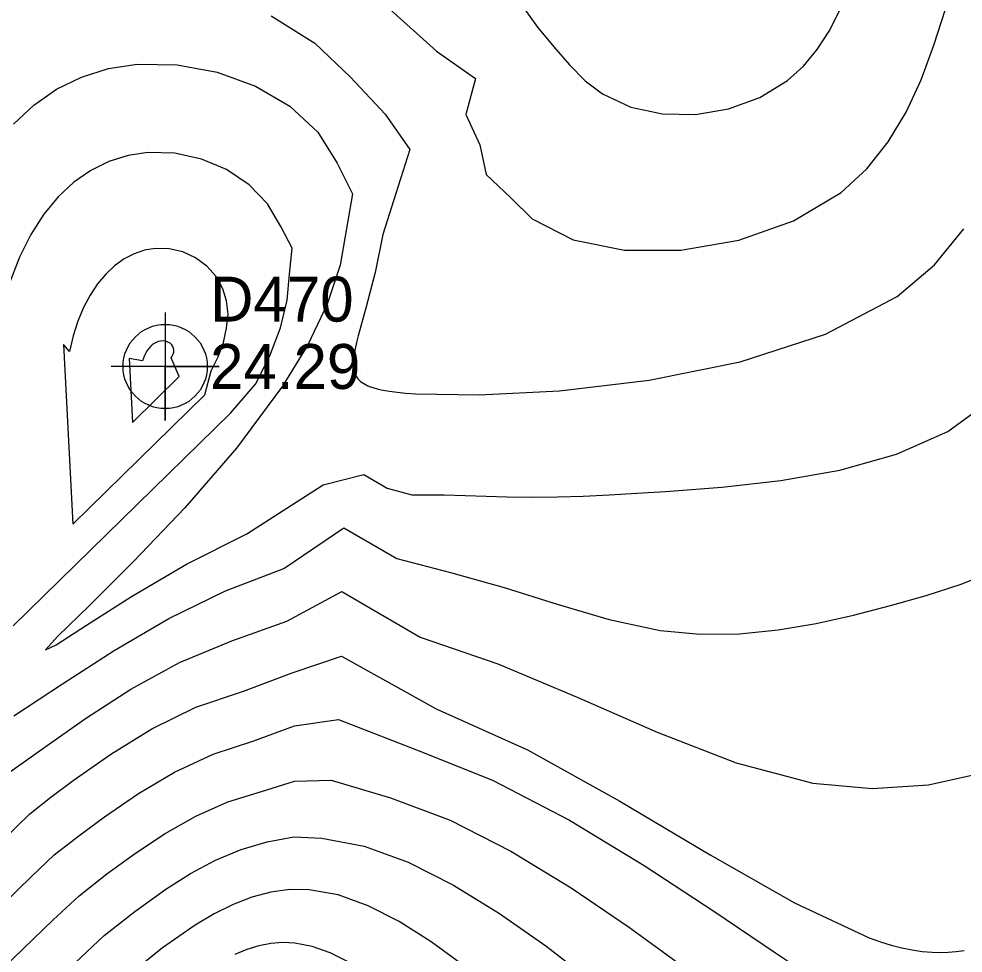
# Model space of a CAD drawing. Extents: x 2356077 to 2359823, y 225951 to 227822.
# Drawn here: x 2356716.3 to 2356768.9, y 226939 to 226991.1 of the extents above; entities that cross this region are included whole.
import ezdxf

# ---------------------------------------------------------------- set-up
doc = ezdxf.new("R2010")
doc.units = 0
for name, color, linetype in [('DTM Contours Major', 7, 'Continuous'), ('DTM Contours Minor', 7, 'Continuous'), ('Exist DTM Regular Point CELL', 7, 'Continuous'), ('Exist DTM Regular Point Cogo Elevation', 7, 'Continuous'), ('Exist DTM Regular Point Cogo Number', 7, 'Continuous'), ('PH Exist DTM Point', 7, 'Continuous')]:
    doc.layers.add(name, color=color, linetype=linetype)

msp = doc.modelspace()

# ---------------------------------------------------------------- linework, layer by layer
at = {"layer": 'DTM Contours Major'}
for points in [[(2356716.024, 226985.191), (2356717.155, 226986.252), (2356718.423, 226987.128), (2356719.815, 226987.808), (2356721.316, 226988.279), (2356722.912, 226988.527), (2356725.134, 226988.5), (2356727.373, 226988.084), (2356729.508, 226987.303), (2356731.415, 226986.182), (2356732.97, 226984.744), (2356734.05, 226983.015), (2356734.908, 226981.299), (2356734.219, 226977.331), (2356733.487, 226975.163), (2356732.407, 226972.908), (2356731.006, 226970.595), (2356728.435, 226967.137), (2356725.559, 226963.817), (2356722.717, 226960.834), (2356720.252, 226958.389), (2356718.504, 226956.685), (2356717.816, 226955.921), (2356718.408, 226956.202), (2356720.092, 226957.29), (2356722.601, 226958.884), (2356725.666, 226960.681), (2356729.019, 226962.379), (2356733.274, 226965.1), (2356735.538, 226965.678), (2356736.833, 226964.921), (2356738.198, 226964.553), (2356740.006, 226964.551), (2356743.514, 226964.435), (2356744.911, 226964.419), (2356746.317, 226964.435), (2356747.746, 226964.478), (2356749.215, 226964.546), (2356750.739, 226964.633), (2356752.333, 226964.737), (2356755.469, 226964.976), (2356758.754, 226965.343), (2356762.042, 226965.926), (2356765.188, 226966.811), (2356768.047, 226968.083), (2356770.473, 226969.83)], [(2356715.459, 226938.194), (2356718.23, 226940.885), (2356719.678, 226942.225), (2356721.223, 226943.438), (2356722.82, 226944.602), (2356724.468, 226945.689), (2356726.178, 226946.656), (2356727.962, 226947.453), (2356729.828, 226948.028), (2356731.677, 226948.606), (2356733.716, 226948.667), (2356737.016, 226947.683), (2356740.333, 226946.426), (2356743.716, 226944.701), (2356747.078, 226942.658), (2356750.334, 226940.449), (2356753.397, 226938.225)]]:
    msp.add_lwpolyline(points, dxfattribs=at)
at = {"layer": 'DTM Contours Minor'}
for points in [[(2356737, 226991.578), (2356739.576, 226989.257), (2356741.758, 226987.723), (2356741.21, 226985.73), (2356741.994, 226984.046), (2356742.353, 226982.378), (2356743.717, 226981.081), (2356744.899, 226979.922), (2356747.199, 226978.753), (2356750.043, 226978.18), (2356753.194, 226978.179), (2356756.414, 226978.729), (2356759.466, 226979.806), (2356762.114, 226981.388), (2356763.545, 226982.698), (2356764.735, 226984.196), (2356765.727, 226985.858), (2356766.561, 226987.661), (2356767.278, 226989.582), (2356767.919, 226991.597)], [(2356744.351, 226991.776), (2356745.197, 226990.593), (2356746.115, 226989.489), (2356746.985, 226988.484), (2356747.868, 226987.605), (2356748.823, 226986.877), (2356750.403, 226986.135), (2356752.163, 226985.754), (2356754.01, 226985.724), (2356755.849, 226986.033), (2356757.588, 226986.67), (2356759.132, 226987.623), (2356760.008, 226988.42), (2356760.772, 226989.341), (2356761.44, 226990.373), (2356762.025, 226991.507)], [(2356730.381, 226991.226), (2356732.812, 226989.692), (2356734.783, 226987.796), (2356736.724, 226985.743), (2356738.1, 226983.781), (2356737.316, 226981.328), (2356736.601, 226979.044), (2356736.172, 226976.934), (2356735.67, 226975.023), (2356735.226, 226973.408), (2356735.132, 226973.033), (2356735.056, 226972.686), (2356734.998, 226972.367), (2356734.963, 226972.076), (2356734.953, 226971.812), (2356734.97, 226971.573), (2356735.016, 226971.364), (2356735.093, 226971.177), (2356735.204, 226971.012), (2356735.35, 226970.866), (2356735.532, 226970.738), (2356735.754, 226970.625), (2356735.914, 226970.562), (2356736.09, 226970.504), (2356736.282, 226970.452), (2356736.492, 226970.403), (2356736.72, 226970.359), (2356736.965, 226970.319), (2356737.399, 226970.262), (2356737.881, 226970.214), (2356738.41, 226970.175), (2356741.958, 226970.11), (2356746.434, 226970.338), (2356751.419, 226970.93), (2356756.493, 226971.957), (2356761.236, 226973.488), (2356765.227, 226975.594), (2356767.305, 226977.352), (2356768.945, 226979.367)], [(2356716.011, 226957.254), (2356728.103, 226969.101), (2356729.501, 226970.717), (2356730.298, 226972.286), (2356730.888, 226973.849), (2356731.258, 226975.378), (2356731.394, 226976.844), (2356731.549, 226978.292), (2356730.915, 226979.484), (2356730.172, 226980.754), (2356729.141, 226981.817), (2356727.891, 226982.654), (2356726.489, 226983.245), (2356725.004, 226983.571), (2356723.506, 226983.612), (2356722.403, 226983.445), (2356721.342, 226983.11), (2356720.332, 226982.61), (2356719.383, 226981.952), (2356718.506, 226981.139), (2356717.709, 226980.177), (2356716.992, 226979.052), (2356716.365, 226977.788), (2356715.826, 226976.392)], [(2356719.328, 226962.915), (2356726.68, 226970.117), (2356727.036, 226971.457), (2356727.428, 226972.24), (2356727.713, 226973.037), (2356727.887, 226973.832), (2356727.975, 226974.616), (2356727.879, 226975.341), (2356727.688, 226976.02), (2356727.314, 226976.709), (2356726.797, 226977.289), (2356726.168, 226977.747), (2356725.457, 226978.071), (2356724.694, 226978.247), (2356723.91, 226978.263), (2356723.321, 226978.163), (2356722.745, 226977.968), (2356722.188, 226977.681), (2356721.658, 226977.305), (2356721.161, 226976.844), (2356720.706, 226976.302), (2356720.292, 226975.673), (2356719.928, 226974.973), (2356719.616, 226974.211), (2356719.357, 226973.395), (2356719.15, 226972.536), (2356718.818, 226972.925), (2356719.328, 226962.915)], [(2356722.645, 226968.575), (2356725.257, 226971.134), (2356724.802, 226972.18), (2356724.871, 226972.274), (2356724.921, 226972.377), (2356724.95, 226972.484), (2356724.958, 226972.594), (2356724.944, 226972.7), (2356724.907, 226972.801), (2356724.838, 226972.903), (2356724.744, 226972.99), (2356724.629, 226973.057), (2356724.497, 226973.101), (2356724.354, 226973.12), (2356724.205, 226973.11), (2356724.09, 226973.082), (2356723.976, 226973.036), (2356723.864, 226972.975), (2356723.756, 226972.897), (2356723.653, 226972.805), (2356723.558, 226972.699), (2356723.47, 226972.579), (2356723.391, 226972.447), (2356723.323, 226972.306), (2356723.265, 226972.159), (2356723.219, 226972.008), (2356722.464, 226972.132), (2356722.645, 226968.575)], [(2356716.049, 226952.241), (2356718.749, 226954.017), (2356721.637, 226955.879), (2356724.676, 226957.661), (2356727.83, 226959.198), (2356731.073, 226960.443), (2356734.427, 226962.712), (2356737.366, 226960.994), (2356740.36, 226960.219), (2356743.345, 226959.39), (2356746.293, 226958.459), (2356749.193, 226957.603), (2356752.03, 226956.996), (2356754.267, 226956.785), (2356756.459, 226956.809), (2356758.609, 226957.024), (2356760.722, 226957.387), (2356762.803, 226957.854), (2356764.854, 226958.383), (2356766.852, 226958.94), (2356768.791, 226959.569), (2356770.636, 226960.323)], [(2356715.671, 226949.012), (2356717.708, 226950.458), (2356720.036, 226952.096), (2356722.56, 226953.733), (2356725.275, 226955.22), (2356728.178, 226956.41), (2356731.256, 226957.507), (2356734.313, 226959.164), (2356738.671, 226956.616), (2356742.992, 226955.142), (2356747.413, 226953.278), (2356751.86, 226951.331), (2356756.258, 226949.629), (2356760.53, 226948.5), (2356763.836, 226948.19), (2356766.972, 226948.397), (2356769.899, 226949.052)], [(2356713.89, 226943.841), (2356716.93, 226946.792), (2356718.113, 226947.714), (2356719.354, 226948.635), (2356721.454, 226950.115), (2356723.727, 226951.519), (2356726.183, 226952.726), (2356728.834, 226953.611), (2356731.539, 226954.643), (2356734.286, 226955.564), (2356739.568, 226952.637), (2356744.645, 226950.345), (2356749.796, 226947.488), (2356754.818, 226944.502), (2356759.509, 226941.822), (2356763.67, 226939.883), (2356764.295, 226939.664), (2356764.901, 226939.477), (2356765.491, 226939.324), (2356766.066, 226939.206), (2356766.628, 226939.122), (2356767.178, 226939.075), (2356767.629, 226939.062), (2356768.075, 226939.075), (2356768.516, 226939.113), (2356768.953, 226939.175)], [(2356714.653, 226940.997), (2356717.028, 226943.302), (2356718.289, 226944.492), (2356719.663, 226945.554), (2356721.096, 226946.612), (2356722.987, 226947.907), (2356724.997, 226949.099), (2356727.136, 226950.107), (2356729.417, 226950.851), (2356731.677, 226951.675), (2356734.127, 226952.042), (2356738.474, 226950.341), (2356742.705, 226948.66), (2356746.98, 226946.432), (2356751.137, 226943.914), (2356755.017, 226941.363), (2356758.459, 226939.036), (2356759.901, 226938.08)], [(2356719.456, 226938.49), (2356721.082, 226940.001), (2356722.785, 226941.354), (2356724.516, 226942.593), (2356725.889, 226943.46), (2356727.28, 226944.206), (2356728.698, 226944.803), (2356730.151, 226945.225), (2356731.629, 226945.504), (2356733.203, 226945.437), (2356735.551, 226944.992), (2356738.001, 226944.092), (2356740.524, 226942.813), (2356743.088, 226941.232), (2356745.663, 226939.425), (2356748.219, 226937.47)], [(2356741.149, 226938.296), (2356739.289, 226939.65), (2356737.497, 226940.783), (2356735.769, 226941.665), (2356734.102, 226942.268), (2356732.494, 226942.561), (2356731.413, 226942.571), (2356730.351, 226942.43), (2356729.301, 226942.15), (2356728.256, 226941.742), (2356727.209, 226941.218), (2356726.151, 226940.588), (2356724.326, 226939.315), (2356722.484, 226937.839)], [(2356734.702, 226938.528), (2356733.665, 226939.047), (2356732.664, 226939.403), (2356731.69, 226939.589), (2356731.023, 226939.615), (2356730.36, 226939.561), (2356729.696, 226939.428), (2356729.026, 226939.221), (2356728.347, 226938.942)]]:
    msp.add_lwpolyline(points, dxfattribs=at)
at = {"layer": 'Exist DTM Regular Point CELL'}
msp.add_lwpolyline([(2356724.473, 226974.694), (2356724.473, 226968.694), (2356724.473, 226971.694), (2356727.473, 226971.694), (2356721.473, 226971.694)], dxfattribs=at)
msp.add_circle((2356724.473, 226971.694), 2.344, dxfattribs=at)
at = {"layer": 'PH Exist DTM Point'}
msp.add_line((2356735.369, 226971.29), (2356735.369, 226971.29), dxfattribs=at)

# ---------------------------------------------------------------- texts
at = {"layer": 'Exist DTM Regular Point Cogo Elevation'}
msp.add_text('24.29', height=2.5, dxfattribs=at).set_placement((2356726.973, 226970.445))
at = {"layer": 'Exist DTM Regular Point Cogo Number'}
msp.add_text('D470', height=2.5, dxfattribs=at).set_placement((2356726.973, 226974.195))

doc.saveas('drawing.dxf')
